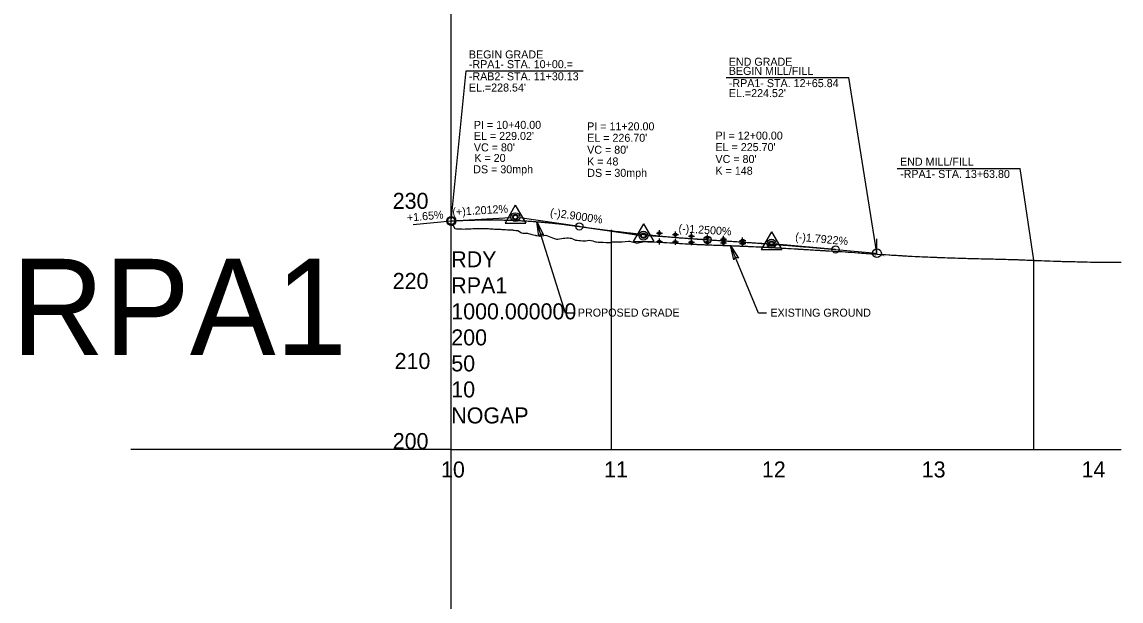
# Model space of a CAD drawing. Extents: x 2115752 to 2121174, y 562881 to 567245.
# Drawn here: x 2116428 to 2117115, y 565412 to 565773 of the extents above; entities that cross this region are included whole.
import ezdxf

# ---------------------------------------------------------------- set-up
doc = ezdxf.new("R2010")
doc.units = 0
for name, color, linetype in [('Exist Profile Cell', 7, 'Continuous'), ('Exist Vertical Profile Ground Line', 7, 'Continuous'), ('Exist Vertical Profile Horizontal Axis Label Major', 7, 'Continuous'), ('Exist Vertical Profile Vertical Axis Label', 7, 'Continuous'), ('Prop PFL VPI Symbol CELL', 7, 'Continuous'), ('Prop Terminator CELL', 7, 'Continuous'), ('Prop Vertical Profile Curve Label', 7, 'Continuous'), ('Prop Vertical Profile Grade', 7, 'Continuous'), ('Prop Vertical Profile Grade Label', 7, 'Continuous'), ('Prop VPI Label', 7, 'Continuous'), ('Scratch_Level_1', 7, 'Continuous')]:
    doc.layers.add(name, color=color, linetype=linetype)

msp = doc.modelspace()

# ---------------------------------------------------------------- linework, layer by layer
at = {"layer": 'Exist Profile Cell'}
for q in [(2116696.3, 565756.42), (2117114.58, 565506.42), (2116696.3, 565506.42)]:
    msp.add_line((2116696.3, 565506.42), q, dxfattribs=at)
at = {"layer": 'Exist Vertical Profile Ground Line'}
for points in [[(2116696.3, 565646.71), (2116697.4, 565646.26), (2116698.51, 565644.42), (2116699.58, 565644.24), (2116699.88, 565644.19), (2116700.67, 565644.2), (2116701.76, 565644.2), (2116702.85, 565644.13), (2116704.19, 565644.07), (2116705.04, 565644.11), (2116705.65, 565644.14), (2116706.13, 565644.16), (2116706.71, 565644.19), (2116707.22, 565644.22), (2116708.31, 565644.28), (2116708.65, 565644.3), (2116709.67, 565644.34), (2116710.49, 565644.37), (2116711.96, 565644.41), (2116712.68, 565644.43), (2116713.95, 565644.46), (2116714.34, 565644.48), (2116714.86, 565644.46), (2116716.06, 565644.42), (2116717.04, 565644.44), (2116718.15, 565644.35), (2116719.45, 565644.32), (2116720.32, 565644.29), (2116721.41, 565644.2), (2116722.5, 565644.13), (2116723.19, 565644.09), (2116723.59, 565644.07), (2116724.29, 565644.04), (2116724.68, 565644.01), (2116725.78, 565643.99), (2116726.32, 565643.97), (2116726.87, 565643.93), (2116727.19, 565643.9), (2116727.96, 565643.86), (2116729.39, 565643.78), (2116730.14, 565643.73), (2116731.35, 565643.66), (2116732.48, 565643.57), (2116733.42, 565643.53), (2116734.51, 565643.48), (2116734.94, 565643.45), (2116735.6, 565643.34), (2116736.69, 565643.24), (2116737.8, 565643.14), (2116738.87, 565642.43), (2116739.64, 565641.93), (2116740.13, 565641.62), (2116741.06, 565641.56), (2116742.15, 565641.49), (2116743.24, 565641.43), (2116743.93, 565641.39), (2116744.33, 565641.29), (2116745.42, 565640.99), (2116746.57, 565640.69), (2116747.61, 565640.45), (2116748.7, 565640.2), (2116749.04, 565640.12), (2116749.79, 565639.98), (2116750.88, 565639.78), (2116751.36, 565639.69), (2116751.97, 565639.76), (2116753.06, 565639.88), (2116754.16, 565640), (2116755.34, 565640.14), (2116756.34, 565639.77), (2116757.43, 565639.36), (2116758.52, 565638.95), (2116759.61, 565638.55), (2116760.7, 565638.15), (2116761.96, 565637.71), (2116762.89, 565637.83), (2116763.98, 565637.97), (2116765.07, 565638.12), (2116766.16, 565638.27), (2116767.25, 565638.43), (2116768.39, 565638.6), (2116769.44, 565638.51), (2116770.53, 565638.42), (2116771.26, 565638.36), (2116771.62, 565638.19), (2116772.71, 565637.66), (2116773.8, 565637.15), (2116774.89, 565637.05), (2116775.99, 565636.94), (2116777.08, 565636.84), (2116778.17, 565636.73), (2116779.26, 565636.63), (2116780.35, 565636.61), (2116781.44, 565636.84), (2116782.54, 565637.02), (2116783.63, 565636.93), (2116784.72, 565636.78), (2116785.81, 565636.24), (2116786.27, 565636.02), (2116786.9, 565635.99), (2116787.99, 565635.94)], [(2116787.99, 565635.94), (2116789.08, 565635.89), (2116791.07, 565635.8), (2116793.06, 565635.7), (2116795.05, 565635.61), (2116795.94, 565635.57), (2116796.62, 565636.05), (2116797.04, 565636.04), (2116798.71, 565636.01), (2116799.03, 565636.01), (2116801.02, 565636), (2116801.91, 565636), (2116803.01, 565636.1), (2116805, 565636.29), (2116806.99, 565636.47), (2116807.54, 565636.52), (2116808.98, 565636.13), (2116810.96, 565635.59), (2116812.05, 565635.32), (2116812.95, 565635.5), (2116814.94, 565635.89), (2116816.93, 565636.22), (2116818.92, 565636.15), (2116820.91, 565636.07), (2116822.9, 565635.99), (2116824.89, 565635.9), (2116826.88, 565635.82), (2116828.87, 565635.73), (2116830.86, 565635.63), (2116832.85, 565635.52), (2116834.31, 565635.44), (2116834.99, 565635.39), (2116836.82, 565635.27), (2116837.99, 565635.19), (2116838.81, 565635.14), (2116839.52, 565635.09), (2116840.38, 565635.03), (2116840.8, 565635), (2116842.29, 565634.92), (2116843.02, 565634.9), (2116843.62, 565634.85), (2116844.78, 565634.79), (2116845.26, 565634.76), (2116846.77, 565634.66), (2116848.76, 565634.58), (2116849.21, 565634.57), (2116849.66, 565634.51), (2116850.75, 565634.45), (2116851.23, 565634.43), (2116852.21, 565634.4), (2116852.85, 565634.37), (2116854.05, 565634.33), (2116854.73, 565634.28), (2116855.84, 565634.19), (2116856.92, 565634.18), (2116858.7, 565634.12), (2116859.05, 565634.11), (2116860.16, 565634.03), (2116860.69, 565634.01), (2116861.31, 565633.99), (2116862.68, 565633.96), (2116863.36, 565633.94), (2116863.79, 565633.94), (2116864.67, 565633.92), (2116865, 565633.91), (2116865.93, 565633.87), (2116866.66, 565633.85), (2116867.35, 565633.82), (2116868.65, 565633.78), (2116869.3, 565633.76), (2116870.64, 565633.71), (2116872.05, 565633.65), (2116872.9, 565633.62), (2116874.17, 565633.57), (2116874.62, 565633.56), (2116874.96, 565633.54), (2116876.18, 565633.49), (2116876.61, 565633.47), (2116877.17, 565633.44), (2116878.74, 565633.38), (2116879.38, 565633.35), (2116879.94, 565633.33), (2116880.59, 565633.31), (2116881.2, 565633.29), (2116881.92, 565633.25), (2116882.57, 565633.21), (2116885.06, 565633.09), (2116886.55, 565633.04), (2116887.65, 565633.01), (2116888.61, 565632.96), (2116890.18, 565632.89), (2116890.53, 565632.87), (2116890.95, 565632.85), (2116892.52, 565632.76), (2116893.35, 565632.71), (2116893.95, 565632.66), (2116894.51, 565632.63), (2116895.45, 565632.58), (2116896.2, 565632.54), (2116896.5, 565632.53), (2116897.07, 565632.5)], [(2116897.07, 565632.5), (2116898.49, 565632.43), (2116899.03, 565632.41), (2116899.38, 565632.39), (2116900.48, 565632.33), (2116900.81, 565632.31), (2116901.85, 565632.25), (2116902.47, 565632.22), (2116902.93, 565632.19), (2116904.64, 565632.09), (2116905.2, 565632.05), (2116906.44, 565631.99), (2116907.07, 565631.95), (2116907.46, 565631.93), (2116908.63, 565631.86), (2116910.42, 565631.76), (2116911.87, 565631.67), (2116912.65, 565631.62), (2116913.03, 565631.59), (2116914.52, 565631.5), (2116915.82, 565631.43), (2116916.41, 565631.39), (2116917.61, 565631.32), (2116918.59, 565631.25), (2116919.47, 565631.2), (2116920.37, 565631.15), (2116921.34, 565631.09), (2116922.36, 565631.03), (2116923.5, 565630.96), (2116924.61, 565630.89), (2116926.34, 565630.79), (2116926.85, 565630.76), (2116927.68, 565630.71), (2116928.32, 565630.67), (2116929.66, 565630.58), (2116930.31, 565630.54), (2116932.34, 565630.42), (2116934.57, 565630.28), (2116935.07, 565630.26), (2116935.71, 565630.21), (2116936.28, 565630.18), (2116937.79, 565630.1), (2116938.27, 565630.07), (2116939.06, 565630.02), (2116940.51, 565629.94), (2116942.25, 565629.83), (2116943.22, 565629.77), (2116944.24, 565629.7), (2116944.8, 565629.67), (2116946.23, 565629.56), (2116948.22, 565629.42), (2116948.63, 565629.39), (2116950.21, 565629.27), (2116951.33, 565629.19), (2116952.47, 565629.1), (2116954.18, 565628.97), (2116955.43, 565628.88), (2116956.17, 565628.83), (2116956.68, 565628.79), (2116958.27, 565628.68), (2116959.36, 565628.61), (2116960.15, 565628.55), (2116962.14, 565628.41), (2116962.45, 565628.39), (2116964.68, 565628.24), (2116966.04, 565628.14), (2116967.39, 565628.07), (2116969.62, 565627.94), (2116970.28, 565627.9), (2116971.19, 565627.85), (2116972.69, 565627.76), (2116973.8, 565627.68), (2116974.38, 565627.65), (2116975.37, 565627.58), (2116975.77, 565627.56), (2116976.84, 565627.5), (2116977.73, 565627.45), (2116978.06, 565627.43), (2116978.76, 565627.39), (2116980.75, 565627.28), (2116981.62, 565627.23), (2116983.36, 565627.14), (2116984.14, 565627.11), (2116986.01, 565627.01), (2116987.12, 565626.95), (2116987.46, 565626.94), (2116988.66, 565626.87), (2116990.31, 565626.8), (2116991.52, 565626.74), (2116993.49, 565626.64), (2116993.96, 565626.62), (2116995.3, 565626.56), (2116996.68, 565626.51), (2116997.25, 565626.49), (2116999.29, 565626.42), (2116999.87, 565626.4), (2117001.22, 565626.35), (2117001.96, 565626.32), (2117003.05, 565626.27), (2117003.48, 565626.26), (2117004.6, 565626.21)], [(2117004.6, 565626.21), (2117006.24, 565626.15), (2117006.74, 565626.14), (2117007.45, 565626.11), (2117009.43, 565626.03), (2117009.83, 565626.01), (2117011.02, 565625.99), (2117012.61, 565625.93), (2117014.52, 565625.87), (2117015.16, 565625.85), (2117015.8, 565625.84), (2117016.95, 565625.81), (2117017.75, 565625.78), (2117018.98, 565625.75), (2117020.39, 565625.72), (2117022.43, 565625.68), (2117023.06, 565625.66), (2117024.86, 565625.62), (2117025.63, 565625.59), (2117027.2, 565625.56), (2117028.54, 565625.53), (2117028.85, 565625.52), (2117031.07, 565625.48), (2117031.73, 565625.46), (2117033.53, 565625.41), (2117034.95, 565625.37), (2117036.17, 565625.34), (2117038.1, 565625.3), (2117038.8, 565625.28), (2117041.42, 565625.21), (2117042.61, 565625.18), (2117044.02, 565625.15), (2117044.48, 565625.13), (2117044.78, 565625.13), (2117046.78, 565625.07), (2117047.23, 565625.06), (2117047.66, 565625.04), (2117048.79, 565625), (2117049.27, 565624.99), (2117050.14, 565624.95), (2117050.85, 565624.93), (2117051.85, 565624.89), (2117054.03, 565624.81), (2117054.49, 565624.79), (2117054.8, 565624.78), (2117055.85, 565624.73), (2117057.22, 565624.67), (2117057.6, 565624.65), (2117059.71, 565624.55), (2117060.41, 565624.52), (2117060.81, 565624.51), (2117062.31, 565624.45), (2117062.83, 565624.43), (2117063.59, 565624.4), (2117064.97, 565624.34), (2117066.78, 565624.27), (2117067.53, 565624.25), (2117068.87, 565624.2), (2117070.1, 565624.16), (2117072.32, 565624.08), (2117072.7, 565624.07), (2117073.15, 565624.05), (2117073.62, 565624.04), (2117075.33, 565623.97), (2117076.34, 565623.94), (2117076.96, 565623.92), (2117077.9, 565623.9), (2117078.99, 565623.87), (2117079.53, 565623.85), (2117080.5, 565623.83), (2117082.81, 565623.77), (2117083.12, 565623.76), (2117085.08, 565623.72), (2117085.9, 565623.7), (2117087.12, 565623.66), (2117088.28, 565623.62), (2117089.08, 565623.61), (2117090.35, 565623.58), (2117091.19, 565623.56), (2117092.28, 565623.53), (2117093.49, 565623.5), (2117095.46, 565623.46), (2117096.06, 565623.44), (2117097.31, 565623.43), (2117098.64, 565623.41), (2117101.4, 565623.38), (2117102, 565623.38), (2117103.83, 565623.36), (2117105.02, 565623.35), (2117105.5, 565623.34), (2117106.4, 565623.34), (2117107.56, 565623.33), (2117108.2, 565623.32), (2117108.97, 565623.31), (2117111.66, 565623.31), (2117112.01, 565623.31), (2117114.15, 565623.32), (2117114.57, 565623.32)]]:
    msp.add_lwpolyline(points, dxfattribs=at)
at = {"layer": 'Prop PFL VPI Symbol CELL'}
for p, q in [((2116736.3, 565659), (2116729.85, 565647.8)), ((2116736.3, 565659), (2116742.8, 565647.8)), ((2116729.85, 565647.8), (2116742.8, 565647.8)), ((2116816.3, 565647.4), (2116809.85, 565636.2)), ((2116816.3, 565647.4), (2116822.8, 565636.2)), ((2116896.3, 565642.4), (2116889.85, 565631.2)), ((2116896.3, 565642.4), (2116902.8, 565631.2)), ((2116809.85, 565636.2), (2116822.8, 565636.2)), ((2116889.85, 565631.2), (2116902.8, 565631.2))]:
    msp.add_line(p, q, dxfattribs=at)
for centre, radius in [((2116736.3, 565651.52), 1.75), ((2116736.3, 565651.52), 1.2), ((2116816.3, 565639.92), 1.75), ((2116816.3, 565639.92), 1.2), ((2116896.3, 565634.92), 1.75), ((2116896.3, 565634.92), 1.2)]:
    msp.add_circle(centre, radius, dxfattribs=at)
at = {"layer": 'Prop Terminator CELL'}
for points in [[(2116750.94, 565639.61), (2116749.74, 565648.66), (2116753.97, 565640.5), (2116752.1, 565641.12)], [(2116872.67, 565624.81), (2116870.64, 565633.71), (2116875.6, 565625.98), (2116873.68, 565626.42)]]:
    msp.add_lwpolyline(points, close=True, dxfattribs=at)
at = {"layer": 'Prop Vertical Profile Curve Label'}
for centre in [(2116696.3, 565649.11), (2116776.3, 565645.72), (2116776.3, 565645.72), (2116856.3, 565637.42), (2116856.3, 565637.42), (2116936.3, 565631.33)]:
    msp.add_circle(centre, 2.25, dxfattribs=at)
at = {"layer": 'Prop Vertical Profile Grade'}
msp.add_line((2116936.3, 565631.33), (2116962.14, 565629.02), dxfattribs=at)
for points in [[(2116696.3, 565649.11), (2116697.9, 565649.21), (2116699.5, 565649.29), (2116701.1, 565649.37), (2116702.7, 565649.44), (2116704.3, 565649.51), (2116705.9, 565649.57), (2116707.5, 565649.62), (2116709.1, 565649.67), (2116710.7, 565649.71), (2116712.3, 565649.75), (2116713.9, 565649.77), (2116715.5, 565649.79), (2116717.1, 565649.81), (2116718.7, 565649.81), (2116720.3, 565649.82), (2116721.9, 565649.81), (2116723.5, 565649.8), (2116725.1, 565649.78), (2116726.7, 565649.75), (2116728.3, 565649.72), (2116729.9, 565649.68), (2116731.5, 565649.64), (2116733.1, 565649.59), (2116734.7, 565649.53), (2116736.3, 565649.46), (2116737.9, 565649.39), (2116739.5, 565649.32), (2116741.1, 565649.23), (2116742.7, 565649.14), (2116744.3, 565649.04), (2116745.9, 565648.94), (2116747.5, 565648.83), (2116749.1, 565648.71), (2116750.7, 565648.59), (2116752.3, 565648.46), (2116753.9, 565648.32), (2116755.5, 565648.18), (2116757.1, 565648.03), (2116758.7, 565647.87), (2116760.3, 565647.71), (2116761.9, 565647.54), (2116763.5, 565647.36), (2116765.1, 565647.18), (2116766.7, 565646.99), (2116768.3, 565646.79), (2116769.9, 565646.59), (2116771.5, 565646.38), (2116773.1, 565646.17), (2116774.7, 565645.94), (2116776.3, 565645.72)], [(2116776.3, 565645.72), (2116777.9, 565645.48), (2116779.5, 565645.26), (2116781.1, 565645.03), (2116782.7, 565644.81), (2116784.3, 565644.59), (2116785.9, 565644.37), (2116787.5, 565644.16), (2116789.1, 565643.94), (2116790.7, 565643.73), (2116792.3, 565643.53), (2116793.9, 565643.32), (2116795.5, 565643.12), (2116797.1, 565642.92), (2116798.7, 565642.73), (2116800.3, 565642.53), (2116801.9, 565642.34), (2116803.5, 565642.15), (2116805.1, 565641.97), (2116806.7, 565641.78), (2116808.3, 565641.6), (2116809.9, 565641.43), (2116811.5, 565641.25), (2116813.1, 565641.08), (2116814.7, 565640.91), (2116816.3, 565640.74), (2116817.9, 565640.58), (2116819.5, 565640.41), (2116821.1, 565640.25), (2116822.7, 565640.1), (2116824.3, 565639.94), (2116825.9, 565639.79), (2116827.5, 565639.64), (2116829.1, 565639.5), (2116830.7, 565639.35), (2116832.3, 565639.21), (2116833.9, 565639.07), (2116835.5, 565638.94), (2116837.1, 565638.81), (2116838.7, 565638.67), (2116840.3, 565638.55), (2116841.9, 565638.42), (2116843.5, 565638.3), (2116845.1, 565638.18), (2116846.7, 565638.06), (2116848.3, 565637.95), (2116849.9, 565637.84), (2116851.5, 565637.73), (2116853.1, 565637.62), (2116854.7, 565637.52), (2116856.3, 565637.42)], [(2116856.3, 565637.42), (2116857.9, 565637.31), (2116859.5, 565637.21), (2116861.1, 565637.11), (2116862.7, 565637.01), (2116864.3, 565636.9), (2116865.9, 565636.8), (2116867.5, 565636.69), (2116869.1, 565636.59), (2116870.7, 565636.48), (2116872.3, 565636.37), (2116873.9, 565636.26), (2116875.5, 565636.15), (2116877.1, 565636.04), (2116878.7, 565635.93), (2116880.3, 565635.82), (2116881.9, 565635.7), (2116883.5, 565635.59), (2116885.1, 565635.47), (2116886.7, 565635.36), (2116888.3, 565635.24), (2116889.9, 565635.12), (2116891.5, 565635.01), (2116893.1, 565634.89), (2116894.7, 565634.77), (2116896.3, 565634.64), (2116897.9, 565634.52), (2116899.5, 565634.4), (2116901.1, 565634.27), (2116902.7, 565634.15), (2116904.3, 565634.02), (2116905.9, 565633.9), (2116907.5, 565633.77), (2116909.1, 565633.64), (2116910.7, 565633.51), (2116912.3, 565633.38), (2116913.9, 565633.25), (2116915.5, 565633.12), (2116917.1, 565632.99), (2116918.7, 565632.86), (2116920.3, 565632.72), (2116921.9, 565632.59), (2116923.5, 565632.45), (2116925.1, 565632.31), (2116926.7, 565632.18), (2116928.3, 565632.04), (2116929.9, 565631.9), (2116931.5, 565631.76), (2116933.1, 565631.62), (2116934.7, 565631.47), (2116936.3, 565631.33)]]:
    msp.add_spline(points, degree=3, dxfattribs=at)
at = {"layer": 'Prop VPI Label'}
for p, q in [((2116696.3, 565649.11), (2116705.5, 565742.92)), ((2116705.5, 565742.92), (2116778.76, 565742.92)), ((2116867.89, 565738.64), (2116944.66, 565738.64)), ((2116962.14, 565629.02), (2116944.66, 565738.64)), ((2116974.86, 565681.92), (2117051.63, 565681.92)), ((2117060.1, 565624.53), (2117051.63, 565681.92)), ((2116672.58, 565646.9), (2116696.3, 565649.11)), ((2116696.3, 565649.11), (2116733.56, 565651.35)), ((2116776.3, 565645.72), (2116739.03, 565651.12)), ((2116776.3, 565645.72), (2116813.58, 565640.31)), ((2116856.3, 565637.42), (2116819.05, 565639.74)), ((2116856.3, 565637.42), (2116893.56, 565635.09)), ((2116936.3, 565631.33), (2116899.04, 565634.67))]:
    msp.add_line(p, q, dxfattribs=at)
for points in [[(2116772.93, 565591.49), (2116767.63, 565591.49), (2116749.74, 565648.66)], [(2116893.17, 565591.58), (2116888.2, 565591.58), (2116870.64, 565633.71)]]:
    msp.add_lwpolyline(points, dxfattribs=at)
for centre in [(2116696.3, 565649.11), (2116736.3, 565651.52), (2116816.3, 565639.92), (2116896.3, 565634.92), (2116962.14, 565629.02)]:
    msp.add_circle(centre, 2.75, dxfattribs=at)
at = {"layer": 'Scratch_Level_1'}
for p, q in [((2116696.3, 565506.42), (2116696.3, 566375.81)), ((2116796.3, 565506.42), (2116796.3, 565643.56)), ((2116824.37, 565641.49), (2116826.3, 565641.49)), ((2116826.3, 565641.49), (2116826.3, 565643.43)), ((2116826.3, 565641.49), (2116828.24, 565641.49)), ((2116826.3, 565639.55), (2116826.3, 565641.49)), ((2116836.3, 565640.56), (2116836.3, 565642.5)), ((2116846.3, 565639.64), (2116846.3, 565641.58)), ((2116856.3, 565638.73), (2116856.3, 565640.67)), ((2116824.37, 565636.28), (2116826.3, 565636.28)), ((2116826.3, 565636.28), (2116826.3, 565638.21)), ((2116826.3, 565636.28), (2116828.24, 565636.28)), ((2116826.3, 565634.34), (2116826.3, 565636.28)), ((2116834.37, 565640.56), (2116836.3, 565640.56)), ((2116834.37, 565636.1), (2116836.3, 565636.1)), ((2116836.3, 565640.56), (2116838.24, 565640.56)), ((2116836.3, 565638.62), (2116836.3, 565640.56)), ((2116836.3, 565636.1), (2116836.3, 565638.03)), ((2116836.3, 565636.1), (2116838.24, 565636.1)), ((2116836.3, 565634.16), (2116836.3, 565636.1)), ((2116844.37, 565639.64), (2116846.3, 565639.64)), ((2116844.37, 565635.89), (2116846.3, 565635.89)), ((2116846.3, 565639.64), (2116848.24, 565639.64)), ((2116846.3, 565637.7), (2116846.3, 565639.64)), ((2116846.3, 565635.89), (2116846.3, 565637.83)), ((2116846.3, 565635.89), (2116848.24, 565635.89)), ((2116846.3, 565633.95), (2116846.3, 565635.89)), ((2116854.37, 565638.73), (2116856.3, 565638.73)), ((2116854.37, 565635.66), (2116856.3, 565635.66)), ((2116856.3, 565638.73), (2116858.24, 565638.73)), ((2116856.3, 565636.79), (2116856.3, 565638.73)), ((2116856.3, 565635.66), (2116856.3, 565637.59)), ((2116856.3, 565635.66), (2116858.24, 565635.66)), ((2116856.3, 565633.72), (2116856.3, 565635.66)), ((2116864.37, 565637.84), (2116866.3, 565637.84)), ((2116864.37, 565635.39), (2116866.3, 565635.39)), ((2116866.3, 565637.84), (2116866.3, 565639.77)), ((2116866.3, 565637.84), (2116868.24, 565637.84)), ((2116866.3, 565635.9), (2116866.3, 565637.84)), ((2116866.3, 565635.39), (2116866.3, 565637.33)), ((2116866.3, 565635.39), (2116868.24, 565635.39)), ((2116866.3, 565633.45), (2116866.3, 565635.39)), ((2116876.3, 565636.81), (2116878.23, 565636.81)), ((2116876.3, 565635.01), (2116878.23, 565635.01)), ((2116878.23, 565636.81), (2116878.23, 565638.75)), ((2116878.23, 565635.01), (2116878.23, 565636.94)), ((2116878.23, 565636.81), (2116880.17, 565636.81)), ((2116878.23, 565634.87), (2116878.23, 565636.81)), ((2116878.23, 565635.01), (2116880.17, 565635.01)), ((2116878.23, 565633.07), (2116878.23, 565635.01)), ((2116962.14, 565628.41), (2116962.14, 565637.87)), ((2116962.14, 565628.41), (2116966.06, 565628.15)), ((2117060.1, 565506.42), (2117060.1, 565624.53)), ((2116696.3, 565506.42), (2116496.27, 565506.42)), ((2116696.3, 564637.02), (2116696.3, 565506.42))]:
    msp.add_line(p, q, dxfattribs=at)
for centre in [(2116826.3, 565641.49), (2116836.3, 565640.56), (2116826.3, 565636.28), (2116836.3, 565636.1), (2116846.3, 565639.64), (2116846.3, 565635.89), (2116856.3, 565638.73), (2116856.3, 565635.66), (2116866.3, 565637.84), (2116866.3, 565635.39), (2116878.23, 565636.81), (2116878.23, 565635.01)]:
    msp.add_circle(centre, 0.949, dxfattribs=at)

# ---------------------------------------------------------------- texts
at = {"layer": 'Exist Profile Cell'}
for s, p in [('RDY', (2116696.3, 565620.17)), ('RPA1', (2116696.3, 565603.92)), ('1000.000000', (2116696.3, 565587.67)), ('200', (2116696.3, 565571.42)), ('50', (2116696.3, 565555.17)), ('10', (2116696.3, 565538.92)), ('NOGAP', (2116696.3, 565522.67))]:
    msp.add_text(s, height=10, dxfattribs=at).set_placement(p)
at = {"layer": 'Exist Vertical Profile Horizontal Axis Label Major'}
for s, p in [('10', (2116689.89, 565488.92)), ('11', (2116791.73, 565488.92)), ('12', (2116890.28, 565488.92)), ('13', (2116990.11, 565488.92)), ('14', (2117089.95, 565488.92))]:
    msp.add_text(s, height=10, dxfattribs=at).set_placement(p)
at = {"layer": 'Exist Vertical Profile Vertical Axis Label'}
for s, height, p in [('230', 10, (2116659.74, 565656.67)), ('RPA1', 60, (2116421.6, 565565.48)), ('220', 10, (2116659.74, 565606.67)), ('210', 10, (2116660.93, 565556.67)), ('200', 10, (2116659.74, 565506.67))]:
    msp.add_text(s, height=height, dxfattribs=at).set_placement(p)
at = {"layer": 'Prop Vertical Profile Curve Label'}
for s, p in [("VC = 80'", (2116710.41, 565692.56)), ("VC = 80'", (2116781.16, 565691.1)), ('K = 20', (2116710.71, 565685.97)), ('K = 48', (2116781.16, 565683.75)), ("VC = 80'", (2116861.3, 565685.29)), ('DS = 30mph', (2116710.02, 565678.89)), ('DS = 30mph', (2116781.23, 565676.67)), ('K = 148', (2116861.3, 565677.97))]:
    msp.add_text(s, height=5, dxfattribs=at).set_placement(p)
at = {"layer": 'Prop Vertical Profile Grade Label'}
for s, rotation, p in [('+1.65%', 5.00151, (2116668.83, 565648.66)), ('(+)1.2012%', 3.4372, (2116697.15, 565652.23)), ('(-)2.9000%', 351.74961, (2116757.76, 565652.17)), ('(-)1.2500%', 356.42367, (2116838.1, 565642.11)), ('(-)1.7922%', 354.87934, (2116910.92, 565636.89))]:
    msp.add_text(s, height=5, rotation=rotation, dxfattribs=at).set_placement(p)
at = {"layer": 'Prop VPI Label'}
for s, p in [('BEGIN GRADE', (2116707.27, 565750.62)), ('END GRADE', (2116869.6, 565746.05)), ('-RPA1- STA. 10+00.=', (2116707.27, 565744.53)), ('BEGIN MILL/FILL', (2116869.6, 565740.33)), ('-RAB2- STA. 11+30.13', (2116707.27, 565736.94)), ('-RPA1- STA. 12+65.84', (2116869.63, 565732.69)), ("EL.=228.54'", (2116707.27, 565729.94)), ("EL.=224.52'", (2116869.63, 565726.44)), ('PI = 10+40.00', (2116710.41, 565706.64)), ('PI = 11+20.00', (2116781.16, 565705.7)), ("EL = 229.02'", (2116710.41, 565699.71)), ("EL = 226.70'", (2116781.16, 565698.55)), ('PI = 12+00.00', (2116861.3, 565699.92)), ("EL = 225.70'", (2116861.3, 565692.73)), ('END MILL/FILL', (2116976.56, 565683.62)), ('-RPA1- STA. 13+63.80', (2116976.6, 565675.98)), ('PROPOSED GRADE', (2116775.35, 565589.39)), ('EXISTING GROUND', (2116895.61, 565589.34))]:
    msp.add_text(s, height=5, dxfattribs=at).set_placement(p)
at = {"layer": 'Scratch_Level_1'}
msp.add_text('-1.3249 %', height=1, rotation=356.21007, dxfattribs=at).set_placement((2116960.58, 565627.28))

doc.saveas('drawing.dxf')
